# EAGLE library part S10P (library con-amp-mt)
AMP MT CONNECTOR
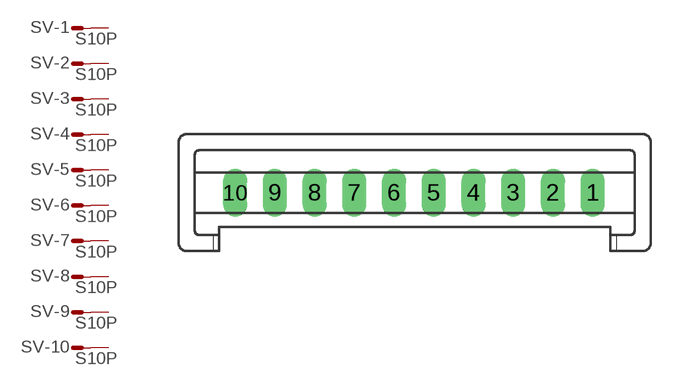
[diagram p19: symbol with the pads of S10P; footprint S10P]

Designator prefix SV; gates -1=M -2=M -3=M -4=M -5=M -6=M -7=M -8=M -9=M -10=M

## S10P (OC_FARNELL: unknown; OC_NEWARK: unknown)  [S10P]
1  -1:S  pas
2  -2:S  pas
3  -3:S  pas
4  -4:S  pas
5  -5:S  pas
6  -6:S  pas
7  -7:S  pas
8  -8:S  pas
9  -9:S  pas
10  -10:S  pas

## Footprint S10P (pad centres in mm)
AMP MT CONNECTOR
drill 1.016 long: 1 11.25,0; 2 8.75,0; 3 6.25,0; 4 3.75,0; 5 1.25,0; 6 -1.25,0; 7 -3.75,0; 8 -6.25,0; 9 -8.75,0; 10 -11.25,0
